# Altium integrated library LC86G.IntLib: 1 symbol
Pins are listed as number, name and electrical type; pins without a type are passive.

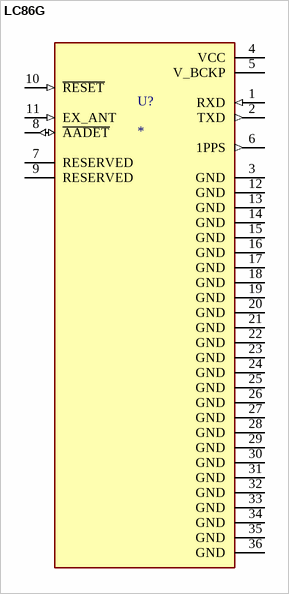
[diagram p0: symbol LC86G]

## LC86G
designator U?
Based on the latest enhanced chipset, the new Quectel LC86G series GNSS module supports concurrent reception of GPS, GLONASS, BDS, Galileo and QZSS. The LC86G series is designed to be compatible with Quectel L80 and L86 modules, allowing for smooth migration between them. Compared with single constellation receivers, by enabling multiple GNSS constellations, the LC86G series increases the number of visible satellites, reduces the time to first fix and improves positioning accuracy, especially when driving through dense urban canyons.
footprint XCVR_LC86G
pins: 1 RXD (in), 2 TXD (out), 3 GND (power), 4 VCC (power), 5 V_BCKP (power), 6 1PPS (out), 7 RESERVED, 8 ~{AADET} (io), 9 RESERVED, 10 ~{RESET} (in), 11 EX_ANT (in), 12 GND (power), 13 GND (power), 14 GND (power), 15 GND (power), 16 GND (power), 17 GND (power), 18 GND (power), 19 GND (power), 20 GND (power), 21 GND (power), 22 GND (power), 23 GND (power), 24 GND (power), 25 GND (power), 26 GND (power), 27 GND (power), 28 GND (power), 29 GND (power), 30 GND (power), 31 GND (power), 32 GND (power), 33 GND (power), 34 GND (power), 35 GND (power), 36 GND (power)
